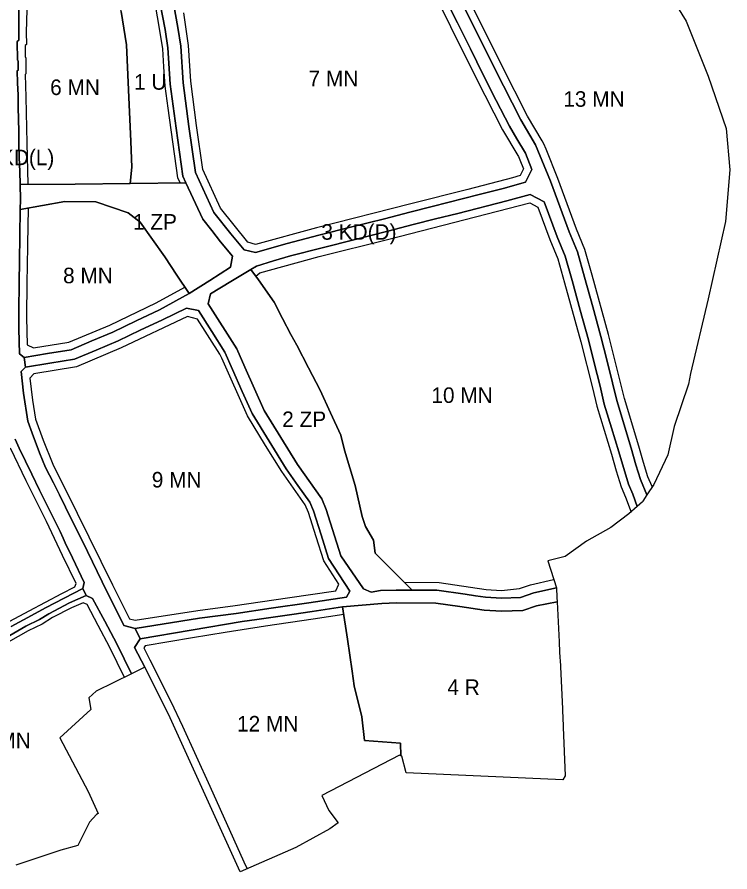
# Model space of a CAD drawing. Extents: x 7437690 to 7439067, y 5547517 to 5548678.
# Drawn here: x 7438518 to 7439067, y 5547588 to 5548247 of the extents above; entities that cross this region are included whole.
import ezdxf

# ---------------------------------------------------------------- set-up
doc = ezdxf.new("R2010")
doc.units = 0
for name, color, linetype in [('linie_rozgraniczajace', 7, 'Continuous'), ('linie_zabudowy_nieprzekraczalne', 7, 'Continuous'), ('oznaczenia_przeznaczen', 7, 'Continuous')]:
    doc.layers.add(name, color=color, linetype=linetype)

msp = doc.modelspace()

# ---------------------------------------------------------------- linework, layer by layer
at = {"layer": 'linie_rozgraniczajace'}
for points in [[(7438593.93, 5548276.99), (7438617.27, 5548286.46), (7438623.99, 5548282.62), (7438628.19, 5548257.38), (7438631.83, 5548237.37), (7438634.11, 5548223.4), (7438635.77, 5548195.26), (7438640.33, 5548161.35), (7438642.96, 5548142.79), (7438645.58, 5548124.22), (7438647.91, 5548119.2), (7438604.99, 5548118.75), (7438606.31, 5548131.32), (7438605.41, 5548151.16), (7438603.62, 5548190.83), (7438602.05, 5548225.68), (7438597.99, 5548251.33)], [(7438520.19, 5548098.68), (7438520.32, 5548106.24), (7438520.02, 5548117.85), (7438562.5, 5548118.3), (7438604.99, 5548118.75), (7438647.91, 5548119.2), (7438660.92, 5548091.17), (7438667.83, 5548082.38), (7438674.73, 5548073.6), (7438683.85, 5548062.66), (7438682.35, 5548054.15), (7438666.35, 5548043.93), (7438650.34, 5548033.72), (7438641.02, 5548047.97), (7438631.71, 5548062.23), (7438612.77, 5548088.94), (7438603.36, 5548096.18), (7438578.58, 5548104.67), (7438554.66, 5548104.74)], [(7438698.12, 5548052.47), (7438702.24, 5548054.99), (7438715.39, 5548058.92), (7438728.54, 5548062.85), (7438752.99, 5548069.15), (7438778.32, 5548075.48), (7438803.65, 5548081.82), (7438823.12, 5548086.98), (7438840.39, 5548091.31), (7438857.67, 5548095.64), (7438895.27, 5548105.2), (7438913.38, 5548110.31), (7438924.22, 5548104.62), (7438934.2, 5548077.64), (7438940.49, 5548062.63), (7438945.69, 5548043.78), (7438951.97, 5548020.94), (7438958.26, 5547998.1), (7438962.76, 5547980.26), (7438967.27, 5547962.42), (7438970.57, 5547948.56), (7438976.16, 5547930.1), (7438981.74, 5547911.65), (7438989.12, 5547886.78), (7438992.57, 5547879.07), (7438995.98, 5547869.62), (7438989.58, 5547863.81), (7438975.71, 5547853.37), (7438956.72, 5547842.85), (7438940.26, 5547830.93), (7438926.89, 5547827.69), (7438933.58, 5547806.72), (7438916.26, 5547802.9), (7438905.84, 5547799.33), (7438891.29, 5547798.74), (7438878.96, 5547799.49), (7438871.12, 5547800.64), (7438863.29, 5547801.79), (7438841.34, 5547805.01), (7438822.46, 5547805.06), (7438793.8, 5547833.58), (7438792.55, 5547843.6), (7438786.39, 5547854.13), (7438783.97, 5547861.92), (7438778.37, 5547885.78), (7438770.24, 5547913.05), (7438767.46, 5547924.55), (7438759.48, 5547941.9), (7438751.5, 5547959.25), (7438742.44, 5547976.56), (7438733.38, 5547993.87), (7438728.78, 5548002.24), (7438722.44, 5548014.67), (7438716.1, 5548027.1), (7438703.91, 5548044.29)], [(7438519.57, 5547987.38), (7438519.15, 5548006.61), (7438519.02, 5548012.27), (7438519.1, 5548019.69), (7438519.33, 5548042.84), (7438519.49, 5548058.58), (7438519.84, 5548078.63), (7438520.19, 5548098.68), (7438554.66, 5548104.74), (7438578.58, 5548104.67), (7438603.36, 5548096.18), (7438612.77, 5548088.94), (7438631.71, 5548062.23), (7438641.02, 5548047.97), (7438650.34, 5548033.72), (7438627.68, 5548021.23), (7438609.65, 5548012.62), (7438591.63, 5548004.01), (7438575.48, 5547997.2), (7438559.34, 5547990.38), (7438541.24, 5547987.46), (7438523.15, 5547984.55)], [(7438665.18, 5548025.97), (7438666.98, 5548033.49), (7438682.55, 5548042.98), (7438698.12, 5548052.47), (7438703.91, 5548044.29), (7438716.1, 5548027.1), (7438722.44, 5548014.67), (7438728.78, 5548002.24), (7438733.38, 5547993.87), (7438742.44, 5547976.56), (7438751.5, 5547959.25), (7438759.48, 5547941.9), (7438767.46, 5547924.55), (7438770.24, 5547913.05), (7438778.37, 5547885.78), (7438783.97, 5547861.92), (7438786.39, 5547854.13), (7438792.55, 5547843.6), (7438793.8, 5547833.58), (7438822.46, 5547805.06), (7438810.17, 5547805.09), (7438797.93, 5547804.67), (7438790.81, 5547803.33), (7438784.89, 5547806.04), (7438767.41, 5547831.46), (7438756.19, 5547867.29), (7438752.63, 5547875.44), (7438734.06, 5547901.88), (7438708.29, 5547943.7), (7438693.44, 5547976.99), (7438687.21, 5547991.05)], [(7438520.93, 5547973.72), (7438524.16, 5547976.93), (7438543.09, 5547980.01), (7438562.02, 5547983.09), (7438578.83, 5547990.18), (7438595.63, 5547997.28), (7438612.77, 5548005.46), (7438629.91, 5548013.64), (7438648.39, 5548022.46), (7438657.73, 5548020.6), (7438667.82, 5548004.6), (7438677.91, 5547988.61), (7438683.85, 5547975.21), (7438691.41, 5547958.25), (7438698.97, 5547941.3), (7438712.11, 5547919.98), (7438725.25, 5547898.66), (7438734.33, 5547885.73), (7438743.41, 5547872.79), (7438746.36, 5547866.06), (7438752.11, 5547847.68), (7438757.86, 5547829.31), (7438774.21, 5547804.3), (7438771.68, 5547799.54), (7438742.66, 5547795.29), (7438713.64, 5547791.03), (7438686.65, 5547787.07), (7438658.3, 5547783.5), (7438608.72, 5547775.52), (7438600.18, 5547777.66), (7438583.49, 5547811.49), (7438572.11, 5547834.72), (7438555.08, 5547869.05), (7438550.36, 5547878.52), (7438545.71, 5547887.83), (7438542.73, 5547893.76), (7438539.75, 5547899.68), (7438535.07, 5547910.96), (7438529.33, 5547926.09), (7438526.16, 5547935.34), (7438522.67, 5547957.04)], [(7438768.69, 5547792.07), (7438799.03, 5547794.7), (7438810.33, 5547795.09), (7438840.59, 5547795.01), (7438859.26, 5547792.27), (7438877.93, 5547789.54), (7438891.19, 5547788.73), (7438907.7, 5547789.4), (7438918.26, 5547793.02), (7438934.12, 5547796), (7438935.69, 5547765.2), (7438935.74, 5547764.2), (7438936.35, 5547752.22), (7438936.4, 5547751.22), (7438938.33, 5547713.38), (7438938.34, 5547713.27), (7438938.37, 5547712.27), (7438938.82, 5547700.28), (7438938.86, 5547699.28), (7438940.25, 5547661.87), (7438938.55, 5547658.79), (7438817.86, 5547664.08), (7438814.49, 5547676.94), (7438813.67, 5547677.3), (7438813.3, 5547686.95), (7438785.76, 5547689.13), (7438783.7, 5547707.33), (7438777.77, 5547731.11), (7438776.12, 5547742.42), (7438774.32, 5547754.84), (7438772.51, 5547767.26)], [(7438608.41, 5547760.8), (7438612.69, 5547767.44), (7438651.99, 5547774.08), (7438691.3, 5547780.71), (7438702.61, 5547782.37), (7438729.59, 5547786.33), (7438745.26, 5547788.63), (7438768.69, 5547792.07), (7438772.51, 5547767.26), (7438774.32, 5547754.84), (7438776.12, 5547742.42), (7438777.77, 5547731.11), (7438783.7, 5547707.33), (7438785.76, 5547689.13), (7438813.3, 5547686.95), (7438813.67, 5547677.3), (7438812.57, 5547677.78), (7438752.87, 5547646.61), (7438758.17, 5547634.9), (7438765.23, 5547625.53), (7438758.97, 5547620.75), (7438732.6, 5547606.48), (7438689.67, 5547587.65), (7438634.59, 5547709.28), (7438616.2, 5547745.65)]]:
    msp.add_lwpolyline(points, close=True, dxfattribs=at)
for points in [[(7439007.84, 5548286.03), (7439033.64, 5548243.79), (7439050.67, 5548201.55), (7439064.64, 5548161.22), (7439067.4, 5548129.26), (7439064.12, 5548089.41), (7439050.67, 5548029.82), (7439037.08, 5547972.2), (7439035.37, 5547963.92), (7439024.44, 5547931.11), (7439019.44, 5547909.33), (7439008.63, 5547886.46), (7439003.41, 5547878.49), (7438998.5, 5547890.31), (7438994.97, 5547901.69), (7438991.34, 5547914.47), (7438980.23, 5547951.17), (7438976.98, 5547964.8), (7438972.45, 5547982.73), (7438967.93, 5548000.65), (7438961.63, 5548023.54), (7438955.33, 5548046.43), (7438949.96, 5548065.9), (7438943.5, 5548081.31), (7438929.03, 5548120.42), (7438917.6, 5548148.43), (7438906.15, 5548167.7), (7438886.11, 5548207.1), (7438866.4, 5548247), (7438853.02, 5548273.67)], [(7438838.53, 5548280.25), (7438857.45, 5548242.55), (7438867.31, 5548222.58), (7438877.17, 5548202.62), (7438887.28, 5548182.75), (7438897.39, 5548162.87), (7438903.2, 5548153.1), (7438909.71, 5548142.13), (7438914.71, 5548129.6), (7438909.79, 5548119.71), (7438892.68, 5548114.86), (7438873.95, 5548110.1), (7438837.92, 5548101), (7438820.62, 5548096.66), (7438801.16, 5548091.5), (7438775.84, 5548085.17), (7438750.53, 5548078.84), (7438725.89, 5548072.49), (7438701.6, 5548065.39), (7438692.74, 5548067.6), (7438682.5, 5548079.91), (7438669.5, 5548096.43), (7438655.28, 5548127.09), (7438650.23, 5548162.72), (7438645.73, 5548196.23), (7438644.06, 5548224.5), (7438641.68, 5548239.08), (7438638.04, 5548259.09)], [(7438638.04, 5548259.09), (7438641.68, 5548239.08), (7438644.06, 5548224.5), (7438645.73, 5548196.23), (7438650.23, 5548162.72), (7438655.28, 5548127.09), (7438669.5, 5548096.43), (7438682.5, 5548079.91), (7438692.74, 5548067.6), (7438701.6, 5548065.39), (7438725.89, 5548072.49), (7438750.53, 5548078.84), (7438775.84, 5548085.17), (7438801.16, 5548091.5), (7438820.62, 5548096.66), (7438837.92, 5548101), (7438873.95, 5548110.1), (7438892.68, 5548114.86), (7438909.79, 5548119.71), (7438914.71, 5548129.6), (7438909.71, 5548142.13), (7438903.2, 5548153.1), (7438897.39, 5548162.87), (7438887.28, 5548182.75), (7438877.17, 5548202.62), (7438867.31, 5548222.58), (7438857.45, 5548242.55), (7438838.53, 5548280.25)], [(7438853.02, 5548273.67), (7438866.4, 5548247), (7438886.11, 5548207.1), (7438906.15, 5548167.7), (7438917.6, 5548148.43), (7438929.03, 5548120.42), (7438943.5, 5548081.31), (7438949.96, 5548065.9), (7438955.33, 5548046.43), (7438961.63, 5548023.54), (7438967.93, 5548000.65), (7438972.45, 5547982.73), (7438976.98, 5547964.8), (7438980.23, 5547951.17), (7438991.34, 5547914.47), (7438994.97, 5547901.69), (7438998.5, 5547890.31), (7439003.41, 5547878.49), (7439000.2, 5547873.58), (7438999.99, 5547873.25), (7438995.98, 5547869.62), (7438992.57, 5547879.07), (7438989.12, 5547886.78), (7438981.74, 5547911.65), (7438976.16, 5547930.1), (7438970.57, 5547948.56), (7438967.27, 5547962.42), (7438962.76, 5547980.26), (7438958.26, 5547998.1), (7438951.97, 5548020.94), (7438945.69, 5548043.78), (7438940.49, 5548062.63), (7438934.2, 5548077.64), (7438924.22, 5548104.62), (7438913.38, 5548110.31), (7438895.27, 5548105.2), (7438857.67, 5548095.64), (7438840.39, 5548091.31), (7438823.12, 5548086.98), (7438803.65, 5548081.82), (7438778.32, 5548075.48)], [(7438519.19, 5548255.12), (7438519.03, 5548229.15), (7438517.81, 5548228.33), (7438518.1, 5548213.84), (7438518.56, 5548213.4), (7438518.57, 5548206.14), (7438517.83, 5548205.5), (7438518.19, 5548196.23), (7438518.54, 5548186.95), (7438518.7, 5548177.58), (7438519.03, 5548158.82), (7438519.19, 5548149.44), (7438519.47, 5548138.64), (7438519.75, 5548127.84), (7438520.02, 5548117.85), (7438520.32, 5548106.24), (7438520.19, 5548098.68), (7438519.84, 5548078.63), (7438519.49, 5548058.58), (7438519.33, 5548042.84), (7438519.1, 5548019.69)], [(7438597.99, 5548251.33), (7438602.05, 5548225.68), (7438603.62, 5548190.83), (7438605.41, 5548151.16), (7438606.31, 5548131.32), (7438604.99, 5548118.75), (7438562.5, 5548118.3), (7438520.02, 5548117.85), (7438519.75, 5548127.84), (7438519.47, 5548138.64), (7438519.19, 5548149.44), (7438519.03, 5548158.82), (7438518.7, 5548177.58), (7438518.54, 5548186.95), (7438518.19, 5548196.23), (7438517.83, 5548205.5), (7438518.57, 5548206.14), (7438518.56, 5548213.4), (7438518.1, 5548213.84), (7438517.81, 5548228.33), (7438519.03, 5548229.15), (7438519.19, 5548255.12)], [(7438523.15, 5547984.55), (7438541.24, 5547987.46), (7438559.34, 5547990.38), (7438575.48, 5547997.2), (7438591.63, 5548004.01), (7438609.65, 5548012.62), (7438627.68, 5548021.23), (7438650.34, 5548033.72), (7438666.35, 5548043.93), (7438682.35, 5548054.15), (7438683.85, 5548062.66), (7438674.73, 5548073.6), (7438667.83, 5548082.38), (7438660.92, 5548091.17), (7438647.91, 5548119.2), (7438645.58, 5548124.22), (7438642.96, 5548142.79), (7438640.33, 5548161.35), (7438635.77, 5548195.26), (7438634.11, 5548223.4), (7438631.83, 5548237.37), (7438628.19, 5548257.38)], [(7438778.32, 5548075.48), (7438752.99, 5548069.15), (7438728.54, 5548062.85), (7438715.39, 5548058.92), (7438702.24, 5548054.99), (7438698.12, 5548052.47), (7438682.55, 5548042.98), (7438666.98, 5548033.49), (7438665.18, 5548025.97), (7438687.21, 5547991.05), (7438693.44, 5547976.99), (7438708.29, 5547943.7), (7438734.06, 5547901.88), (7438752.63, 5547875.44), (7438756.19, 5547867.29), (7438767.41, 5547831.46), (7438784.89, 5547806.04), (7438790.81, 5547803.33), (7438797.93, 5547804.67), (7438810.17, 5547805.09), (7438822.46, 5547805.06), (7438841.34, 5547805.01), (7438863.29, 5547801.79), (7438871.12, 5547800.64), (7438878.96, 5547799.49), (7438891.29, 5547798.74), (7438905.84, 5547799.33), (7438916.26, 5547802.9), (7438933.58, 5547806.72), (7438933.95, 5547799.34), (7438934.12, 5547796), (7438918.26, 5547793.02), (7438907.7, 5547789.4), (7438891.19, 5547788.73), (7438877.93, 5547789.54), (7438859.26, 5547792.27), (7438840.59, 5547795.01), (7438810.33, 5547795.09), (7438799.03, 5547794.7), (7438768.69, 5547792.07), (7438745.26, 5547788.63), (7438729.59, 5547786.33), (7438702.61, 5547782.37), (7438691.3, 5547780.71), (7438651.99, 5547774.08), (7438612.69, 5547767.44), (7438608.72, 5547775.52), (7438658.3, 5547783.5), (7438686.65, 5547787.07), (7438713.64, 5547791.03), (7438742.66, 5547795.29), (7438771.68, 5547799.54), (7438774.21, 5547804.3), (7438757.86, 5547829.31), (7438752.11, 5547847.68), (7438746.36, 5547866.06), (7438743.41, 5547872.79), (7438734.33, 5547885.73), (7438725.25, 5547898.66), (7438712.11, 5547919.98), (7438698.97, 5547941.3), (7438691.41, 5547958.25), (7438683.85, 5547975.21), (7438677.91, 5547988.61), (7438667.82, 5548004.6), (7438657.73, 5548020.6), (7438648.39, 5548022.46), (7438629.91, 5548013.64), (7438612.77, 5548005.46), (7438595.63, 5547997.28), (7438578.83, 5547990.18), (7438562.02, 5547983.09), (7438543.09, 5547980.01), (7438524.16, 5547976.93), (7438523.15, 5547984.55)], [(7438519.1, 5548019.69), (7438519.02, 5548012.27), (7438519.15, 5548006.61), (7438519.57, 5547987.38), (7438523.15, 5547984.55), (7438524.16, 5547976.93), (7438520.93, 5547973.72), (7438522.67, 5547957.04), (7438526.16, 5547935.34), (7438529.33, 5547926.09), (7438535.07, 5547910.96), (7438539.75, 5547899.68), (7438542.73, 5547893.76), (7438545.71, 5547887.83), (7438550.36, 5547878.52), (7438555.08, 5547869.05), (7438572.11, 5547834.72), (7438583.49, 5547811.49), (7438600.18, 5547777.66), (7438608.72, 5547775.52), (7438612.69, 5547767.44), (7438608.41, 5547760.8), (7438616.2, 5547745.65), (7438606.06, 5547740.36), (7438600.36, 5547752.07), (7438594.74, 5547763.61), (7438585.39, 5547781.02), (7438576.03, 5547798.44), (7438570.96, 5547800.81), (7438568.38, 5547806.15), (7438569.57, 5547810.85), (7438560.37, 5547829.88), (7438558.05, 5547834.81), (7438555.72, 5547839.73), (7438553.3, 5547845.04), (7438550.87, 5547850.35), (7438547.54, 5547857.04), (7438535.11, 5547882.01), (7438529.09, 5547894.37), (7438519.32, 5547914.44), (7438516.29, 5547921.54)], [(7438516.29, 5547921.54), (7438519.32, 5547914.44), (7438529.09, 5547894.37), (7438535.11, 5547882.01), (7438547.54, 5547857.04), (7438550.87, 5547850.35), (7438553.3, 5547845.04), (7438555.72, 5547839.73), (7438558.05, 5547834.81), (7438560.37, 5547829.88), (7438569.57, 5547810.85), (7438568.38, 5547806.15), (7438554.02, 5547798.79), (7438539.66, 5547791.44), (7438528.84, 5547785.53), (7438513.14, 5547777.05)], [(7438513.14, 5547777.05), (7438528.84, 5547785.53), (7438539.66, 5547791.44), (7438554.02, 5547798.79), (7438568.38, 5547806.15), (7438570.96, 5547800.81), (7438558.22, 5547795.12), (7438542.19, 5547786.82), (7438535.05, 5547782.35), (7438524.42, 5547777.28), (7438509.09, 5547768.33)], [(7438509.09, 5547768.33), (7438524.42, 5547777.28), (7438535.05, 5547782.35), (7438542.19, 5547786.82), (7438558.22, 5547795.12), (7438570.96, 5547800.81), (7438576.03, 5547798.44), (7438585.39, 5547781.02), (7438594.74, 5547763.61), (7438600.36, 5547752.07), (7438606.06, 5547740.36), (7438578.62, 5547727.04), (7438573.04, 5547721.95), (7438574.71, 5547712.89), (7438550.68, 5547691.2), (7438572.66, 5547649.75), (7438580.26, 5547632.71), (7438578.94, 5547632.05), (7438573.71, 5547625.93), (7438564.64, 5547607.92), (7438551.53, 5547604.42), (7438516.71, 5547592.74)]]:
    msp.add_lwpolyline(points, dxfattribs=at)
at = {"layer": 'linie_zabudowy_nieprzekraczalne'}
for points in [[(7439007.52, 5547884.77), (7439007.42, 5547885.05), (7439004.12, 5547892.43), (7439000.72, 5547903.4), (7438997.1, 5547916.15), (7438986.02, 5547952.73), (7438982.8, 5547966.23), (7438973.73, 5548002.18), (7438961.11, 5548048.03), (7438955.64, 5548067.87), (7438949.08, 5548083.52), (7438934.64, 5548122.55), (7438925.81, 5548145.15), (7438924.02, 5548149.37), (7438922.76, 5548151.5), (7438911.41, 5548170.6), (7438891.47, 5548209.79), (7438871.77, 5548249.68), (7438858.39, 5548276.36), (7438833.84, 5548325.23), (7438817.59, 5548356.43), (7438818.29, 5548359), (7438825.9, 5548363.8), (7438883.72, 5548402.3)], [(7438643.41, 5548119.15), (7438641.75, 5548122.93), (7438634.2, 5548176.89), (7438631.94, 5548193.74), (7438630.97, 5548208.7), (7438630.15, 5548222.68), (7438627.89, 5548236.69), (7438620.8, 5548277.55), (7438616.83, 5548279.8), (7438600.6, 5548273.22), (7438588.94, 5548270.16), (7438558.04, 5548265.45), (7438533, 5548260.28), (7438525.15, 5548252.57), (7438524.88, 5548235.47), (7438525.05, 5548225.93), (7438523.87, 5548225.19), (7438523.98, 5548216.61), (7438524.52, 5548215.41), (7438524.57, 5548203.41), (7438523.94, 5548202.86), (7438524.57, 5548185.17), (7438525.18, 5548149.68), (7438526.01, 5548118.19)], [(7438838.73, 5548266.49), (7438852.08, 5548239.88), (7438871.81, 5548199.93), (7438892.13, 5548159.98), (7438903.85, 5548140.27), (7438904.35, 5548139.42), (7438905.44, 5548136.85), (7438908.15, 5548129.9), (7438905.69, 5548124.94), (7438899.74, 5548123.1), (7438865.4, 5548114.12), (7438821.28, 5548103.02), (7438748.6, 5548084.54), (7438701.47, 5548071.61), (7438695.77, 5548073.35), (7438674.65, 5548099.59), (7438661.01, 5548129.4), (7438656.18, 5548163.54), (7438651.65, 5548197.75), (7438650.03, 5548225.16), (7438646.42, 5548250.46)], [(7438526.21, 5548099.7), (7438525.72, 5548071.7), (7438525.45, 5548054.71), (7438525.33, 5548042.77), (7438525.05, 5548015.21), (7438525.42, 5547994.22), (7438530.53, 5547991.81), (7438557.67, 5547996.19), (7438589.17, 5548009.49), (7438625.09, 5548026.64), (7438647.09, 5548038.78)], [(7438701.87, 5548047.17), (7438704.84, 5548049.65), (7438750.6, 5548062.34), (7438804.43, 5548075.83), (7438913.08, 5548103.69), (7438919.39, 5548100.38), (7438928.61, 5548075.44), (7438934.81, 5548060.66), (7438939.91, 5548042.18), (7438952.46, 5547996.57), (7438961.44, 5547960.99), (7438964.78, 5547946.99), (7438975.99, 5547909.96), (7438979.63, 5547897.14), (7438983.5, 5547884.66), (7438987, 5547876.82), (7438991.25, 5547865.07)], [(7438685.91, 5547793.03), (7438726.25, 5547798.94), (7438763.58, 5547804.42), (7438765.89, 5547809.72), (7438754.21, 5547827.59), (7438748.41, 5547846.12), (7438742.48, 5547864.94), (7438739.91, 5547870.82), (7438721.91, 5547896.46), (7438709.28, 5547916.67), (7438695.43, 5547939.43), (7438675.59, 5547983.98), (7438674.19, 5547987.1), (7438656.97, 5548014.09), (7438649.17, 5548016.19), (7438598.09, 5547991.8), (7438563.69, 5547977.28), (7438530.64, 5547971.95), (7438527.51, 5547968.49), (7438529.55, 5547951.62), (7438531.98, 5547936.84), (7438537.81, 5547920.66), (7438545.21, 5547902.18), (7438564.1, 5547864.37), (7438591.36, 5547809.09), (7438604.32, 5547782.84), (7438608.91, 5547781.74), (7438657.14, 5547789.39), (7438685.91, 5547793.03)], [(7438512.16, 5547781.05), (7438527.11, 5547789.14), (7438552.17, 5547802.34), (7438562.24, 5547807.64), (7438563.2, 5547810.13), (7438552.85, 5547831.76), (7438540.39, 5547857.94), (7438524.88, 5547889.31), (7438512.75, 5547914.54)], [(7438816.41, 5547811.08), (7438843.34, 5547810.78), (7438879.58, 5547805.46), (7438891.35, 5547804.75), (7438905.15, 5547806.18), (7438913.62, 5547809.04), (7438931.47, 5547813.33)], [(7438600.67, 5547737.73), (7438589.4, 5547760.88), (7438580.28, 5547777.84), (7438571.69, 5547793.85), (7438568.67, 5547795.26), (7438559.75, 5547791.42), (7438545.1, 5547783.83), (7438536.98, 5547778.84), (7438526.18, 5547773.69), (7438510.91, 5547764.77), (7438494.19, 5547757.3), (7438479.75, 5547753.29), (7438468.97, 5547748.01), (7438450.63, 5547738.86), (7438435.19, 5547730.64), (7438419.34, 5547724.49), (7438415.85, 5547719.05), (7438416.96, 5547689.99), (7438417.57, 5547674.16), (7438417.48, 5547660.48), (7438417.38, 5547645.61), (7438418.44, 5547628.08)], [(7438769.6, 5547786.14), (7438746.13, 5547782.7), (7438709.31, 5547777.29), (7438678.19, 5547772.41), (7438653.05, 5547768.17), (7438616.41, 5547761.93), (7438615.39, 5547760.42), (7438620.03, 5547751.36), (7438636.34, 5547719.13), (7438645.4, 5547699.97), (7438666.35, 5547653.7), (7438692.69, 5547595.52), (7438695.16, 5547590.06)]]:
    msp.add_lwpolyline(points, dxfattribs=at)

# ---------------------------------------------------------------- texts
at = {"layer": 'oznaczenia_przeznaczen'}
for s, p in [('7 MN', (7438742.51, 5548193.76)), ('6 MN', (7438543.25, 5548186.93)), ('1 U', (7438607.94, 5548191.04)), ('13 MN', (7438938.93, 5548177.87)), ('1 KD(L)', (7438491.18, 5548132.81)), ('1 ZP', (7438607.14, 5548083.08)), ('3 KD(D)', (7438752.37, 5548075.31)), ('8 MN', (7438553.23, 5548041.72)), ('10 MN', (7438837.23, 5547949.4)), ('2 ZP', (7438722.18, 5547930.8)), ('9 MN', (7438621.63, 5547884.17)), ('4 R', (7438849.55, 5547724.15)), ('12 MN', (7438687.38, 5547695.95)), ('11 MN', (7438481.04, 5547683.02))]:
    msp.add_text(s, height=12, dxfattribs=at).set_placement(p)

doc.saveas('drawing.dxf')
